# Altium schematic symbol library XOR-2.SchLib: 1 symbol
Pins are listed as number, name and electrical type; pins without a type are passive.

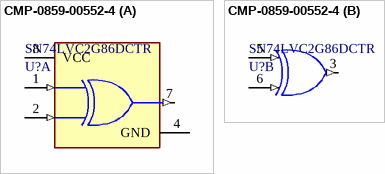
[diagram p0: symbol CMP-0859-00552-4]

## CMP-0859-00552-4
designator U?, comment SN74LVC2G86DCTR
IC GATE XOR 2CH 2-INP SM8; Number of Bits: 2; High Level Output Current: -32mA; Logic Function: XOR GATE; Turn-On Delay Time: 3.6ns; Low Level Output Current: 32mA; Number of Output Lines: 1; Quiescent Current: 10uA; Max Supply Voltage: 5.5V; Schmitt Trigger Input: No; Min Supply Voltage: 1.65V
footprint FP-DCT0008A-MFG
footprint FP-DCT0008A-IPC_A
footprint FP-DCT0008A-IPC_C
footprint FP-DCT0008A-IPC_B
part A pins: 1 1A (in), 2 1B (in), 4 GND (power), 7 1Y (out), 8 VCC (power)
part B pins: 3 2Y (out), 5 2A (in), 6 2B (in)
